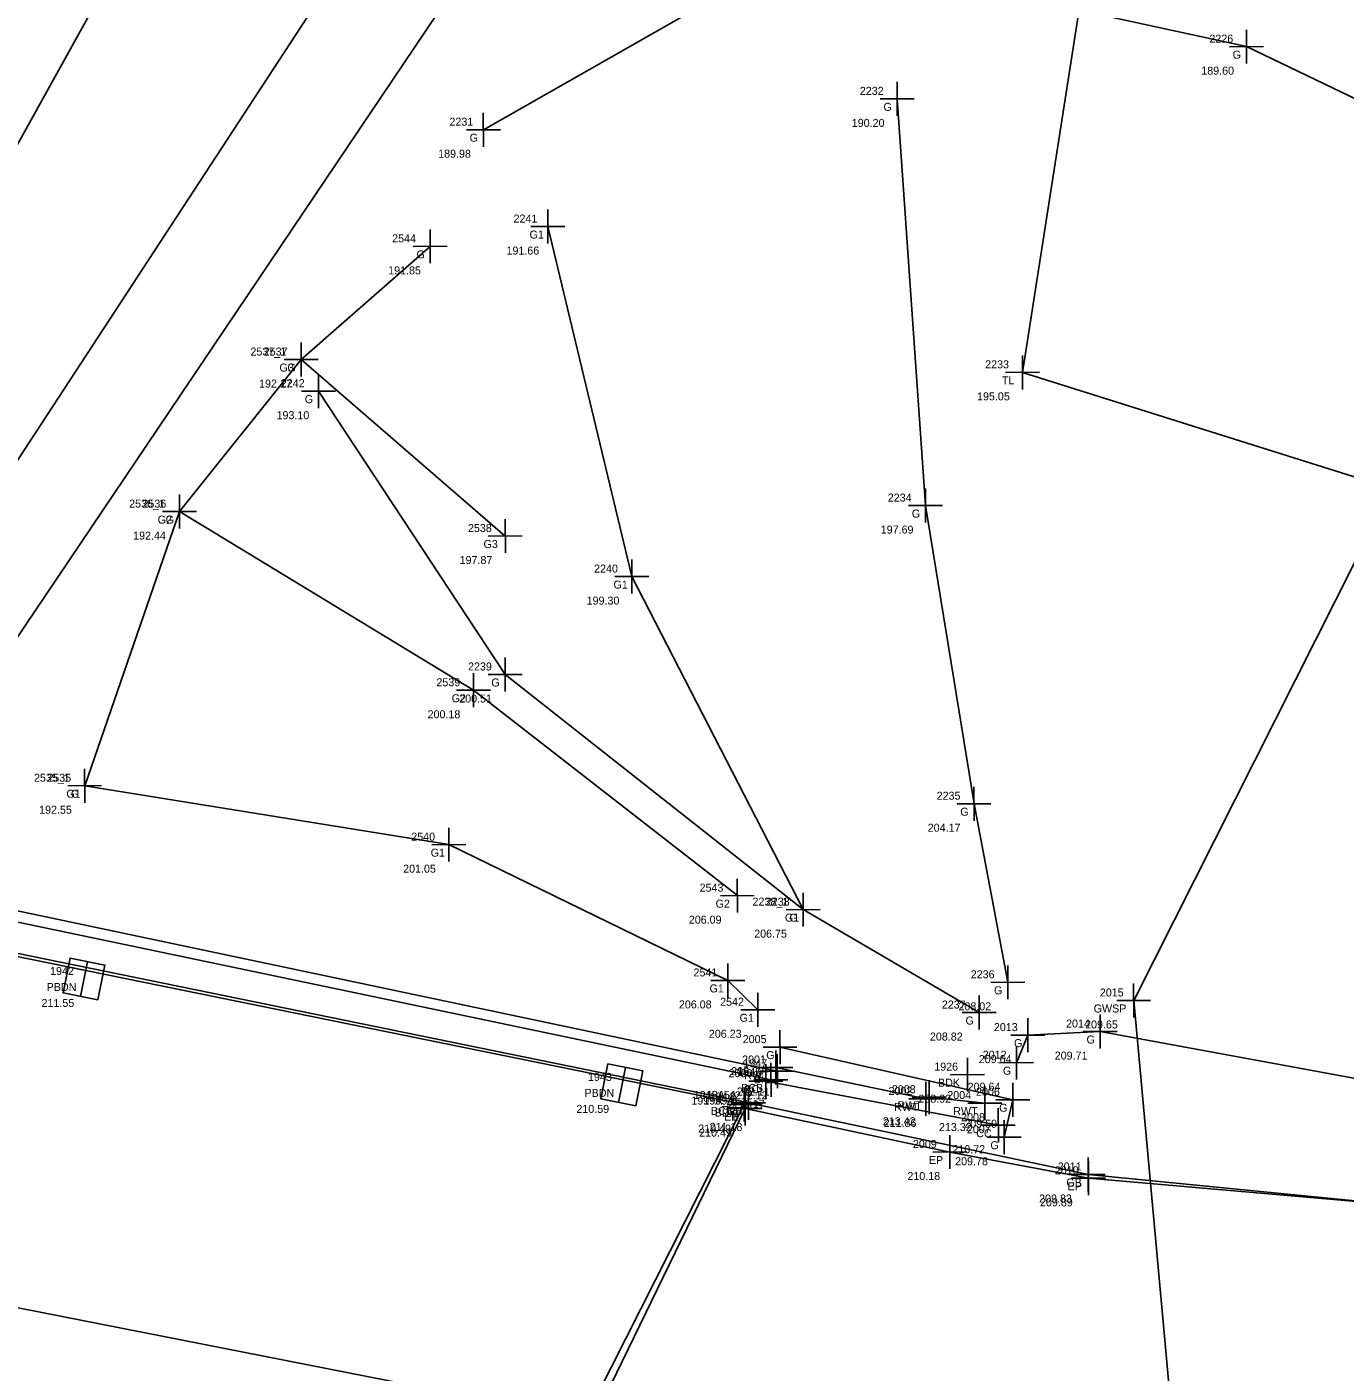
# Model space of a CAD drawing. Extents: x 1155460 to 1157069, y 590691 to 591363.
# Drawn here: x 1156454.8 to 1156504.2, y 591071.2 to 591121.6 of the extents above; entities that cross this region are included whole.
import ezdxf

# ---------------------------------------------------------------- set-up
doc = ezdxf.new("R2010")
doc.units = 0
for name, color, linetype in [('Default', 7, 'Continuous'), ('S_Bridge_Centerline', 7, 'Continuous'), ('S_Bridge_Curb', 7, 'Continuous'), ('S_Bridge_Deck', 7, 'Continuous'), ('S_Bridge_Downspout', 7, 'Continuous'), ('S_Bridge_Rail', 7, 'Continuous'), ('S_Curb_Type_2', 7, 'Continuous'), ('S_Field_Code', 7, 'Continuous'), ('S_Ground_Elevation', 7, 'Continuous'), ('S_Ground_LevelString', 7, 'Continuous'), ('S_Guardrail_Beam', 7, 'Continuous'), ('S_Point_Elevation', 7, 'Continuous'), ('S_Point_Name', 7, 'Continuous'), ('S_RetWall_Top', 7, 'Continuous'), ('S_Roadway_Edge_Pavement', 7, 'Continuous'), ('S_Survey_Shot', 7, 'Continuous'), ('S_Trees_TreeLine', 7, 'Continuous'), ('S_Utilities_GuyWire3', 7, 'Continuous'), ('S_Utilities_Pole_Support3', 7, 'Continuous')]:
    doc.layers.add(name, color=color, linetype=linetype)

msp = doc.modelspace()

# ---------------------------------------------------------------- linework, layer by layer
at = {"layer": 'Default'}
for p, q in [((1156456.962, 591085.928), (1156456.962, 591085.928)), ((1156477.119, 591081.957), (1156477.119, 591081.957))]:
    msp.add_line(p, q, dxfattribs=at)
at = {"layer": 'S_Bridge_Centerline'}
msp.add_lwpolyline([(1156315.508, 591101.371), (1156372.408, 591090.24), (1156431.554, 591078.114), (1156475.254, 591069.515)], dxfattribs=at)
at = {"layer": 'S_Bridge_Curb'}
for points in [[(1156322.515, 591115.068), (1156379.89, 591103.405), (1156438.845, 591091.327), (1156482.706, 591082.146)], [(1156322.364, 591113.705), (1156379.878, 591102.14), (1156481.869, 591081.283)]]:
    msp.add_lwpolyline(points, dxfattribs=at)
at = {"layer": 'S_Bridge_Deck'}
msp.add_line((1156490.067, 591082.341), (1156490.067, 591082.341), dxfattribs=at)
msp.add_lwpolyline([(1156321.636, 591113.83), (1156379.075, 591102.191), (1156438.058, 591090.105), (1156481.699, 591081.221), (1156469.523, 591057.135), (1156425.816, 591065.905), (1156367.048, 591078.105), (1156309.431, 591089.995)], close=True, dxfattribs=at)
at = {"layer": 'S_Bridge_Downspout'}
for p, q in [((1156456.831, 591085.274), (1156457.092, 591086.581)), ((1156476.988, 591081.303), (1156477.25, 591082.611))]:
    msp.add_line(p, q, dxfattribs=at)
for points in [[(1156457.485, 591085.143), (1156456.177, 591085.405), (1156456.439, 591086.712), (1156457.746, 591086.451)], [(1156477.642, 591081.173), (1156476.335, 591081.434), (1156476.596, 591082.741), (1156477.903, 591082.48)]]:
    msp.add_lwpolyline(points, close=True, dxfattribs=at)
at = {"layer": 'S_Bridge_Rail'}
msp.add_lwpolyline([(1156322.645, 591115.567), (1156380.051, 591104.023), (1156439.002, 591091.746), (1156482.943, 591082.468)], dxfattribs=at)
at = {"layer": 'S_Curb_Type_2'}
msp.add_lwpolyline([(1156482.512, 591082.096), (1156491.228, 591080.447)], dxfattribs=at)
at = {"layer": 'S_Ground_Elevation'}
for points in [[(1156446.1, 591102.129), (1156460.785, 591128.628), (1156475.249, 591153.141), (1156494.452, 591191.477), (1156503.913, 591212.172), (1156527.833, 591260.817), (1156554.25, 591307.73), (1156559.036, 591316.061)], [(1156451.333, 591100.585), (1156466.797, 591124.244), (1156478.78, 591139.071), (1156484.221, 591146.593), (1156495.783, 591161.711), (1156501.582, 591166.648), (1156503.661, 591171.39)], [(1156453.899, 591097.887), (1156471.874, 591124.605), (1156479.098, 591129.912), (1156484.701, 591129.916), (1156487.573, 591134.245), (1156487.206, 591143.21), (1156501.642, 591159.812), (1156507.402, 591164.881), (1156511.281, 591166.984)], [(1156994.312, 591026.354), (1156988.281, 591011.67), (1156982.157, 591006.699), (1156976.222, 591006.261), (1156935.59, 591012.529), (1156909.286, 591020.249), (1156879.276, 591021.544), (1156853.942, 591026.061), (1156816.445, 591035.649), (1156768.114, 591049.43), (1156727.412, 591060.658), (1156689.215, 591071.126), (1156661.947, 591076.437), (1156626.722, 591088.15), (1156604.058, 591089.806), (1156567.292, 591097.74), (1156529.864, 591109.36), (1156512.279, 591115.236), (1156500.524, 591120.875), (1156488.74, 591123.45), (1156482.404, 591123.727), (1156471.928, 591117.762)], [(1156487.438, 591118.918), (1156488.501, 591103.673), (1156490.316, 591092.497), (1156491.579, 591085.803)], [(1156483.914, 591088.527), (1156477.49, 591101.011), (1156474.345, 591114.131)], [(1156456.987, 591093.172), (1156460.537, 591103.447), (1156465.101, 591109.146), (1156469.939, 591113.389)], [(1156465.101, 591109.146), (1156472.751, 591102.532)], [(1156490.513, 591084.67), (1156483.914, 591088.527), (1156472.741, 591097.341), (1156465.752, 591107.961)], [(1156460.537, 591103.447), (1156471.555, 591096.75), (1156481.446, 591089.051)], [(1156456.987, 591093.172), (1156470.638, 591090.963), (1156481.089, 591085.874), (1156482.215, 591084.774)], [(1156491.913, 591082.79), (1156492.329, 591083.824), (1156495.048, 591083.957), (1156506.736, 591081.81), (1156549.796, 591072.079), (1156594.701, 591064.294), (1156643.47, 591053.992), (1156692.982, 591043.457), (1156741.529, 591033.483), (1156787.931, 591023.885), (1156837.64, 591013.684), (1156874.149, 591006.125), (1156886.147, 591007.107), (1156898.915, 591006.968), (1156908.962, 591008.2), (1156912.663, 591006.47), (1156934.598, 591002.519), (1156962.056, 590995.598), (1156977.261, 590993.461), (1156984.027, 590995.095), (1156994.336, 590998.898), (1156998.327, 591004.238), (1157007.944, 591024.295)], [(1156483.044, 591083.374), (1156491.773, 591081.402), (1156491.446, 591079.996)]]:
    msp.add_lwpolyline(points, dxfattribs=at)
at = {"layer": 'S_Ground_LevelString'}
msp.add_line((1156481.735, 591081.07), (1156481.735, 591081.07), dxfattribs=at)
msp.add_lwpolyline([(1156481.735, 591081.07), (1156476.043, 591069.35)], dxfattribs=at)
at = {"layer": 'S_Guardrail_Beam'}
msp.add_lwpolyline([(1156481.869, 591081.283), (1156494.59, 591078.6), (1156506.597, 591077.41), (1156549.743, 591070.029), (1156594.66, 591061.958), (1156643.746, 591051.962), (1156692.997, 591041.75), (1156740.961, 591032.095), (1156787.757, 591022.456), (1156837.395, 591011.945), (1156873.883, 591004.183), (1156883.647, 591002.789), (1156896.653, 591001.52), (1156903.637, 591001.645), (1156908.578, 591003.006)], dxfattribs=at)
at = {"layer": 'S_RetWall_Top'}
msp.add_lwpolyline([(1156482.892, 591082.61), (1156488.509, 591081.432), (1156488.634, 591081.495), (1156490.724, 591081.277)], dxfattribs=at)
at = {"layer": 'S_Roadway_Edge_Pavement'}
msp.add_lwpolyline([(1156481.735, 591081.07), (1156489.409, 591079.442), (1156494.61, 591078.457), (1156506.597, 591077.41), (1156549.576, 591069.784), (1156594.668, 591061.67), (1156643.299, 591051.737), (1156692.849, 591041.437), (1156740.745, 591031.573), (1156787.596, 591022.093), (1156837.369, 591011.662), (1156873.731, 591003.888), (1156883.52, 591002.412), (1156896.577, 591000.843), (1156903.209, 591001.187), (1156906.725, 591001.448), (1156912.328, 591002.901), (1156934.046, 590996.44), (1156960.261, 590988.118), (1156974.358, 590983.975), (1157002.341, 590977.221), (1157022.261, 590972.908), (1157044.277, 590968.579), (1157068.612, 590963.118)], dxfattribs=at)
at = {"layer": 'S_Survey_Shot'}
for p, q in [((1156500.526, 591120.239), (1156500.523, 591121.511)), ((1156499.888, 591120.874), (1156501.16, 591120.876)), ((1156500.524, 591120.875), (1156500.524, 591120.875)), ((1156487.44, 591118.282), (1156487.437, 591119.554)), ((1156486.802, 591118.916), (1156488.074, 591118.919)), ((1156487.438, 591118.918), (1156487.438, 591118.918)), ((1156471.929, 591117.126), (1156471.926, 591118.398)), ((1156471.291, 591117.761), (1156472.564, 591117.763)), ((1156471.928, 591117.762), (1156471.928, 591117.762)), ((1156474.347, 591113.495), (1156474.344, 591114.767)), ((1156469.94, 591112.753), (1156469.938, 591114.026)), ((1156473.709, 591114.13), (1156474.982, 591114.133)), ((1156474.345, 591114.131), (1156474.345, 591114.131)), ((1156469.303, 591113.388), (1156470.575, 591113.391)), ((1156469.939, 591113.389), (1156469.939, 591113.389)), ((1156465.102, 591108.51), (1156465.099, 591109.782)), ((1156465.102, 591108.51), (1156465.099, 591109.782)), ((1156464.464, 591109.145), (1156465.737, 591109.147)), ((1156464.464, 591109.145), (1156465.737, 591109.147)), ((1156465.101, 591109.146), (1156465.101, 591109.146)), ((1156465.101, 591109.146), (1156465.101, 591109.146)), ((1156492.137, 591108.03), (1156492.134, 591109.303)), ((1156465.753, 591107.324), (1156465.751, 591108.597)), ((1156491.499, 591108.665), (1156492.771, 591108.668)), ((1156492.135, 591108.667), (1156492.135, 591108.667)), ((1156465.116, 591107.959), (1156466.388, 591107.962)), ((1156465.752, 591107.961), (1156465.752, 591107.961)), ((1156488.502, 591103.037), (1156488.5, 591104.309)), ((1156460.539, 591102.811), (1156460.536, 591104.083)), ((1156460.539, 591102.811), (1156460.536, 591104.083)), ((1156459.901, 591103.446), (1156461.174, 591103.449)), ((1156459.901, 591103.446), (1156461.174, 591103.449)), ((1156460.537, 591103.447), (1156460.537, 591103.447)), ((1156460.537, 591103.447), (1156460.537, 591103.447)), ((1156487.865, 591103.672), (1156489.137, 591103.674)), ((1156488.501, 591103.673), (1156488.501, 591103.673)), ((1156472.752, 591101.896), (1156472.749, 591103.169)), ((1156472.114, 591102.531), (1156473.387, 591102.534)), ((1156472.751, 591102.532), (1156472.751, 591102.532)), ((1156477.492, 591100.374), (1156477.489, 591101.647)), ((1156476.854, 591101.009), (1156478.126, 591101.012)), ((1156477.49, 591101.011), (1156477.49, 591101.011)), ((1156472.743, 591096.705), (1156472.74, 591097.978)), ((1156471.556, 591096.113), (1156471.554, 591097.386)), ((1156472.105, 591097.34), (1156473.377, 591097.343)), ((1156472.741, 591097.341), (1156472.741, 591097.341)), ((1156470.919, 591096.748), (1156472.191, 591096.751)), ((1156471.555, 591096.75), (1156471.555, 591096.75)), ((1156456.988, 591092.536), (1156456.986, 591093.808)), ((1156456.988, 591092.536), (1156456.986, 591093.808)), ((1156456.351, 591093.171), (1156457.623, 591093.174)), ((1156456.351, 591093.171), (1156457.623, 591093.174)), ((1156456.987, 591093.172), (1156456.987, 591093.172)), ((1156456.987, 591093.172), (1156456.987, 591093.172)), ((1156490.317, 591091.86), (1156490.315, 591093.133)), ((1156489.68, 591092.495), (1156490.952, 591092.498)), ((1156490.316, 591092.497), (1156490.316, 591092.497)), ((1156470.64, 591090.327), (1156470.637, 591091.599)), ((1156470.002, 591090.961), (1156471.275, 591090.964)), ((1156470.638, 591090.963), (1156470.638, 591090.963)), ((1156481.447, 591088.415), (1156481.444, 591089.687)), ((1156480.809, 591089.05), (1156482.082, 591089.052)), ((1156481.446, 591089.051), (1156481.446, 591089.051)), ((1156483.916, 591087.891), (1156483.913, 591089.163)), ((1156483.916, 591087.891), (1156483.913, 591089.163)), ((1156483.278, 591088.525), (1156484.55, 591088.528)), ((1156483.278, 591088.525), (1156484.55, 591088.528)), ((1156483.914, 591088.527), (1156483.914, 591088.527)), ((1156483.914, 591088.527), (1156483.914, 591088.527)), ((1156481.09, 591085.238), (1156481.088, 591086.51)), ((1156491.581, 591085.167), (1156491.578, 591086.439)), ((1156480.453, 591085.872), (1156481.725, 591085.875)), ((1156481.089, 591085.874), (1156481.089, 591085.874)), ((1156490.943, 591085.802), (1156492.216, 591085.805)), ((1156491.579, 591085.803), (1156491.579, 591085.803)), ((1156496.301, 591084.486), (1156496.298, 591085.758)), ((1156482.216, 591084.138), (1156482.213, 591085.41)), ((1156490.514, 591084.034), (1156490.512, 591085.306)), ((1156481.578, 591084.773), (1156482.851, 591084.776)), ((1156482.215, 591084.774), (1156482.215, 591084.774)), ((1156489.877, 591084.669), (1156491.149, 591084.671)), ((1156490.513, 591084.67), (1156490.513, 591084.67)), ((1156495.664, 591085.121), (1156496.936, 591085.123)), ((1156496.3, 591085.122), (1156496.3, 591085.122)), ((1156492.33, 591083.188), (1156492.328, 591084.461)), ((1156495.049, 591083.32), (1156495.047, 591084.593)), ((1156483.046, 591082.738), (1156483.043, 591084.01)), ((1156491.693, 591083.823), (1156492.965, 591083.826)), ((1156492.329, 591083.824), (1156492.329, 591083.824)), ((1156494.412, 591083.955), (1156495.684, 591083.958)), ((1156495.048, 591083.957), (1156495.048, 591083.957)), ((1156482.408, 591083.372), (1156483.681, 591083.375)), ((1156482.893, 591081.974), (1156482.89, 591083.246)), ((1156483.044, 591083.374), (1156483.044, 591083.374)), ((1156491.914, 591082.154), (1156491.911, 591083.426)), ((1156482.513, 591081.459), (1156482.51, 591082.732)), ((1156482.708, 591081.51), (1156482.705, 591082.783)), ((1156482.945, 591081.832), (1156482.942, 591083.104)), ((1156490.069, 591081.705), (1156490.066, 591082.977)), ((1156491.277, 591082.789), (1156492.549, 591082.791)), ((1156491.913, 591082.79), (1156491.913, 591082.79)), ((1156482.07, 591082.145), (1156483.343, 591082.148)), ((1156482.255, 591082.608), (1156483.528, 591082.611)), ((1156482.307, 591082.467), (1156483.58, 591082.47)), ((1156482.706, 591082.146), (1156482.706, 591082.146)), ((1156482.892, 591082.61), (1156482.892, 591082.61)), ((1156482.943, 591082.468), (1156482.943, 591082.468)), ((1156488.635, 591080.858), (1156488.633, 591082.131)), ((1156489.431, 591082.34), (1156490.703, 591082.343)), ((1156490.067, 591082.341), (1156490.067, 591082.341)), ((1156481.701, 591080.585), (1156481.698, 591081.857)), ((1156481.736, 591080.433), (1156481.734, 591081.706)), ((1156481.736, 591080.433), (1156481.734, 591081.706)), ((1156481.87, 591080.647), (1156481.868, 591081.919)), ((1156481.87, 591080.647), (1156481.868, 591081.919)), ((1156481.876, 591082.094), (1156483.148, 591082.097)), ((1156482.512, 591082.096), (1156482.512, 591082.096)), ((1156488.51, 591080.796), (1156488.508, 591082.068)), ((1156490.725, 591080.641), (1156490.722, 591081.913)), ((1156491.775, 591080.765), (1156491.772, 591082.038)), ((1156481.063, 591081.22), (1156482.335, 591081.223)), ((1156481.233, 591081.282), (1156482.505, 591081.284)), ((1156481.233, 591081.282), (1156482.505, 591081.284)), ((1156481.699, 591081.221), (1156481.699, 591081.221)), ((1156481.869, 591081.283), (1156481.869, 591081.283)), ((1156481.869, 591081.283), (1156481.869, 591081.283)), ((1156487.873, 591081.431), (1156489.145, 591081.433)), ((1156487.998, 591081.493), (1156489.27, 591081.496)), ((1156488.509, 591081.432), (1156488.509, 591081.432)), ((1156488.634, 591081.495), (1156488.634, 591081.495)), ((1156490.088, 591081.276), (1156491.36, 591081.278)), ((1156490.724, 591081.277), (1156490.724, 591081.277)), ((1156491.137, 591081.4), (1156492.41, 591081.403)), ((1156491.773, 591081.402), (1156491.773, 591081.402)), ((1156481.099, 591081.068), (1156482.371, 591081.071)), ((1156481.099, 591081.068), (1156482.371, 591081.071)), ((1156481.735, 591081.07), (1156481.735, 591081.07)), ((1156481.735, 591081.07), (1156481.735, 591081.07)), ((1156491.229, 591079.81), (1156491.226, 591081.083)), ((1156491.447, 591079.359), (1156491.444, 591080.632)), ((1156490.591, 591080.445), (1156491.864, 591080.448)), ((1156491.228, 591080.447), (1156491.228, 591080.447)), ((1156489.41, 591078.806), (1156489.408, 591080.078)), ((1156490.809, 591079.994), (1156492.082, 591079.997)), ((1156491.446, 591079.996), (1156491.446, 591079.996)), ((1156488.773, 591079.441), (1156490.045, 591079.443)), ((1156489.409, 591079.442), (1156489.409, 591079.442)), ((1156494.591, 591077.963), (1156494.589, 591079.236)), ((1156493.954, 591078.598), (1156495.226, 591078.601)), ((1156494.59, 591078.6), (1156494.59, 591078.6)), ((1156494.611, 591077.821), (1156494.609, 591079.094)), ((1156493.974, 591078.456), (1156495.246, 591078.459)), ((1156494.61, 591078.457), (1156494.61, 591078.457))]:
    msp.add_line(p, q, dxfattribs=at)
at = {"layer": 'S_Trees_TreeLine'}
msp.add_lwpolyline([(1156626.722, 591088.15), (1156602.462, 591086.491), (1156567.292, 591097.74), (1156529.906, 591096.777), (1156492.135, 591108.667), (1156496.742, 591138.205), (1156511.563, 591158.025), (1156535.411, 591162.838)], dxfattribs=at)
at = {"layer": 'S_Utilities_GuyWire3'}
msp.add_lwpolyline([(1156510.688, 591113.641), (1156496.3, 591085.122)], dxfattribs=at)
at = {"layer": 'S_Utilities_Pole_Support3'}
msp.add_line((1156496.3, 591085.122), (1156496.3, 591085.122), dxfattribs=at)
msp.add_lwpolyline([(1156496.3, 591085.122), (1156500.074, 591043.779)], dxfattribs=at)

# ---------------------------------------------------------------- texts
at = {"layer": 'S_Field_Code'}
for s, p in [('G', (1156500.009, 591120.425)), ('G', (1156486.923, 591118.468)), ('G', (1156471.413, 591117.312)), ('G1', (1156473.66, 591113.681)), ('G', (1156469.424, 591112.939)), ('G3', (1156464.286, 591108.696)), ('G', (1156464.586, 591108.696)), ('TL', (1156491.363, 591108.217)), ('G', (1156465.237, 591107.511)), ('G2', (1156459.723, 591102.997)), ('G', (1156460.023, 591102.997)), ('G', (1156487.986, 591103.223)), ('G3', (1156471.936, 591102.082)), ('G1', (1156476.805, 591100.561)), ('G', (1156472.226, 591096.891)), ('G2', (1156470.74, 591096.3)), ('G1', (1156456.302, 591092.722)), ('G', (1156456.472, 591092.722)), ('G', (1156489.801, 591092.047)), ('G1', (1156469.953, 591090.513)), ('G2', (1156480.631, 591088.601)), ('G1', (1156483.229, 591088.077)), ('G', (1156483.399, 591088.077)), ('PBDN', (1156455.561, 591085.478)), ('G1', (1156480.404, 591085.424)), ('G', (1156491.064, 591085.353)), ('GWSP', (1156494.8, 591084.672)), ('G1', (1156481.53, 591084.324)), ('G', (1156489.998, 591084.22)), ('G', (1156491.814, 591083.374)), ('G', (1156494.533, 591083.507)), ('G', (1156482.529, 591082.924)), ('G', (1156491.398, 591082.34)), ('RWT', (1156481.706, 591082.16)), ('BIL', (1156482.072, 591082.018)), ('BDK', (1156488.966, 591081.891)), ('PBDN', (1156475.718, 591081.507)), ('BCB', (1156481.591, 591081.696)), ('CC', (1156481.683, 591081.646)), ('BCB5', (1156480.454, 591080.833)), ('GB', (1156481.054, 591080.833)), ('RWT', (1156487.323, 591080.982)), ('RWT', (1156487.448, 591081.045)), ('RWT', (1156489.538, 591080.827)), ('G', (1156491.259, 591080.952)), ('BDK', (1156480.598, 591080.771)), ('EP', (1156480.948, 591080.62)), ('L', (1156481.262, 591080.62)), ('CC', (1156490.398, 591079.997)), ('G', (1156490.931, 591079.546)), ('EP', (1156488.623, 591078.992)), ('GB', (1156493.775, 591078.15)), ('EP', (1156493.823, 591078.007))]:
    msp.add_text(s, height=0.3, dxfattribs=at).set_placement(p)
at = {"layer": 'S_Point_Elevation'}
for s, p in [('189.60', (1156498.833, 591119.825)), ('190.20', (1156485.735, 591117.868)), ('189.98', (1156470.234, 591116.712)), ('191.66', (1156472.796, 591113.081)), ('191.85', (1156468.361, 591112.339)), ('192.17', (1156463.521, 591108.096)), ('192.17', (1156463.521, 591108.096)), ('195.05', (1156490.43, 591107.617)), ('193.10', (1156464.177, 591106.911)), ('197.69', (1156486.82, 591102.623)), ('192.44', (1156458.802, 591102.397)), ('192.44', (1156458.802, 591102.397)), ('197.87', (1156471.038, 591101.482)), ('199.30', (1156475.799, 591099.961)), ('200.51', (1156471.024, 591096.291)), ('200.18', (1156469.838, 591095.7)), ('192.55', (1156455.279, 591092.122)), ('192.55', (1156455.279, 591092.122)), ('204.17', (1156488.58, 591091.447)), ('201.05', (1156468.921, 591089.913)), ('206.09', (1156479.627, 591088.001)), ('206.75', (1156482.077, 591087.477)), ('206.75', (1156482.077, 591087.477)), ('211.55', (1156455.37, 591084.878)), ('206.08', (1156479.256, 591084.824)), ('208.02', (1156489.732, 591084.753)), ('209.65', (1156494.479, 591084.072)), ('206.23', (1156480.379, 591083.724)), ('208.82', (1156488.664, 591083.62)), ('209.71', (1156493.341, 591082.907)), ('206.20', (1156481.212, 591082.324)), ('209.64', (1156490.494, 591082.774)), ('212.12', (1156481.351, 591081.418)), ('212.11', (1156481.43, 591081.56)), ('209.64', (1156490.078, 591081.74)), ('210.59', (1156475.414, 591080.907)), ('211.12', (1156481.05, 591081.046)), ('211.17', (1156481.242, 591081.096)), ('208.92', (1156488.232, 591081.291)), ('213.42', (1156486.898, 591080.445)), ('211.86', (1156486.931, 591080.382)), ('209.59', (1156489.953, 591080.352)), ('210.49', (1156479.98, 591080.171)), ('210.49', (1156480.015, 591080.02)), ('210.49', (1156480.015, 591080.02)), ('211.18', (1156480.407, 591080.233)), ('211.18', (1156480.407, 591080.233)), ('213.32', (1156489.002, 591080.227)), ('210.72', (1156489.506, 591079.397)), ('209.78', (1156489.608, 591078.946)), ('210.18', (1156487.82, 591078.392)), ('209.83', (1156492.755, 591077.55)), ('209.89', (1156492.789, 591077.407))]:
    msp.add_text(s, height=0.3, dxfattribs=at).set_placement(p)
at = {"layer": 'S_Point_Name'}
for s, p in [('2226', (1156499.138, 591121.025)), ('2232', (1156486.037, 591119.068)), ('2231', (1156470.657, 591117.912)), ('2241', (1156473.06, 591114.281)), ('2544', (1156468.51, 591113.539)), ('2537_1', (1156463.199, 591109.296)), ('2537', (1156463.697, 591109.296)), ('2233', (1156490.734, 591108.817)), ('2242', (1156464.337, 591108.111)), ('2536_1', (1156458.653, 591103.597)), ('2536', (1156459.151, 591103.597)), ('2234', (1156487.086, 591103.823)), ('2538', (1156471.35, 591102.682)), ('2240', (1156476.078, 591101.161)), ('2239', (1156471.355, 591097.492)), ('2539', (1156470.168, 591096.9)), ('2535_1', (1156455.088, 591093.322)), ('2535', (1156455.586, 591093.322)), ('2235', (1156488.915, 591092.647)), ('2540', (1156469.226, 591091.113)), ('2543', (1156480.031, 591089.201)), ('2238_1', (1156482.015, 591088.677)), ('2238', (1156482.513, 591088.677)), ('1942', (1156455.691, 591086.078)), ('2541', (1156479.804, 591086.024)), ('2236', (1156490.193, 591085.953)), ('2542', (1156480.8, 591084.924)), ('2015', (1156495.031, 591085.272)), ('2237', (1156489.11, 591084.82)), ('2013', (1156491.061, 591083.974)), ('2014', (1156493.766, 591084.107)), ('2005', (1156481.648, 591083.524)), ('2012', (1156490.644, 591082.94)), ('2001', (1156481.626, 591082.76)), ('1947', (1156481.67, 591082.618)), ('1926', (1156488.825, 591082.491)), ('1943', (1156475.848, 591082.107)), ('2000', (1156481.118, 591082.246)), ('1946', (1156481.45, 591082.296)), ('1945A_1', (1156479.814, 591081.433)), ('1945A', (1156480.268, 591081.433)), ('1944', (1156480.414, 591081.371)), ('2002', (1156487.113, 591081.582)), ('2003', (1156487.238, 591081.645)), ('2004', (1156489.314, 591081.427)), ('2006', (1156490.392, 591081.552)), ('1999A_1', (1156479.723, 591081.22)), ('1999A', (1156480.176, 591081.22)), ('2008', (1156489.832, 591080.597)), ('2007', (1156490.047, 591080.146)), ('2009', (1156488.027, 591079.592)), ('2010', (1156493.344, 591078.607)), ('2011', (1156493.452, 591078.75))]:
    msp.add_text(s, height=0.3, dxfattribs=at).set_placement(p)

doc.saveas('drawing.dxf')
